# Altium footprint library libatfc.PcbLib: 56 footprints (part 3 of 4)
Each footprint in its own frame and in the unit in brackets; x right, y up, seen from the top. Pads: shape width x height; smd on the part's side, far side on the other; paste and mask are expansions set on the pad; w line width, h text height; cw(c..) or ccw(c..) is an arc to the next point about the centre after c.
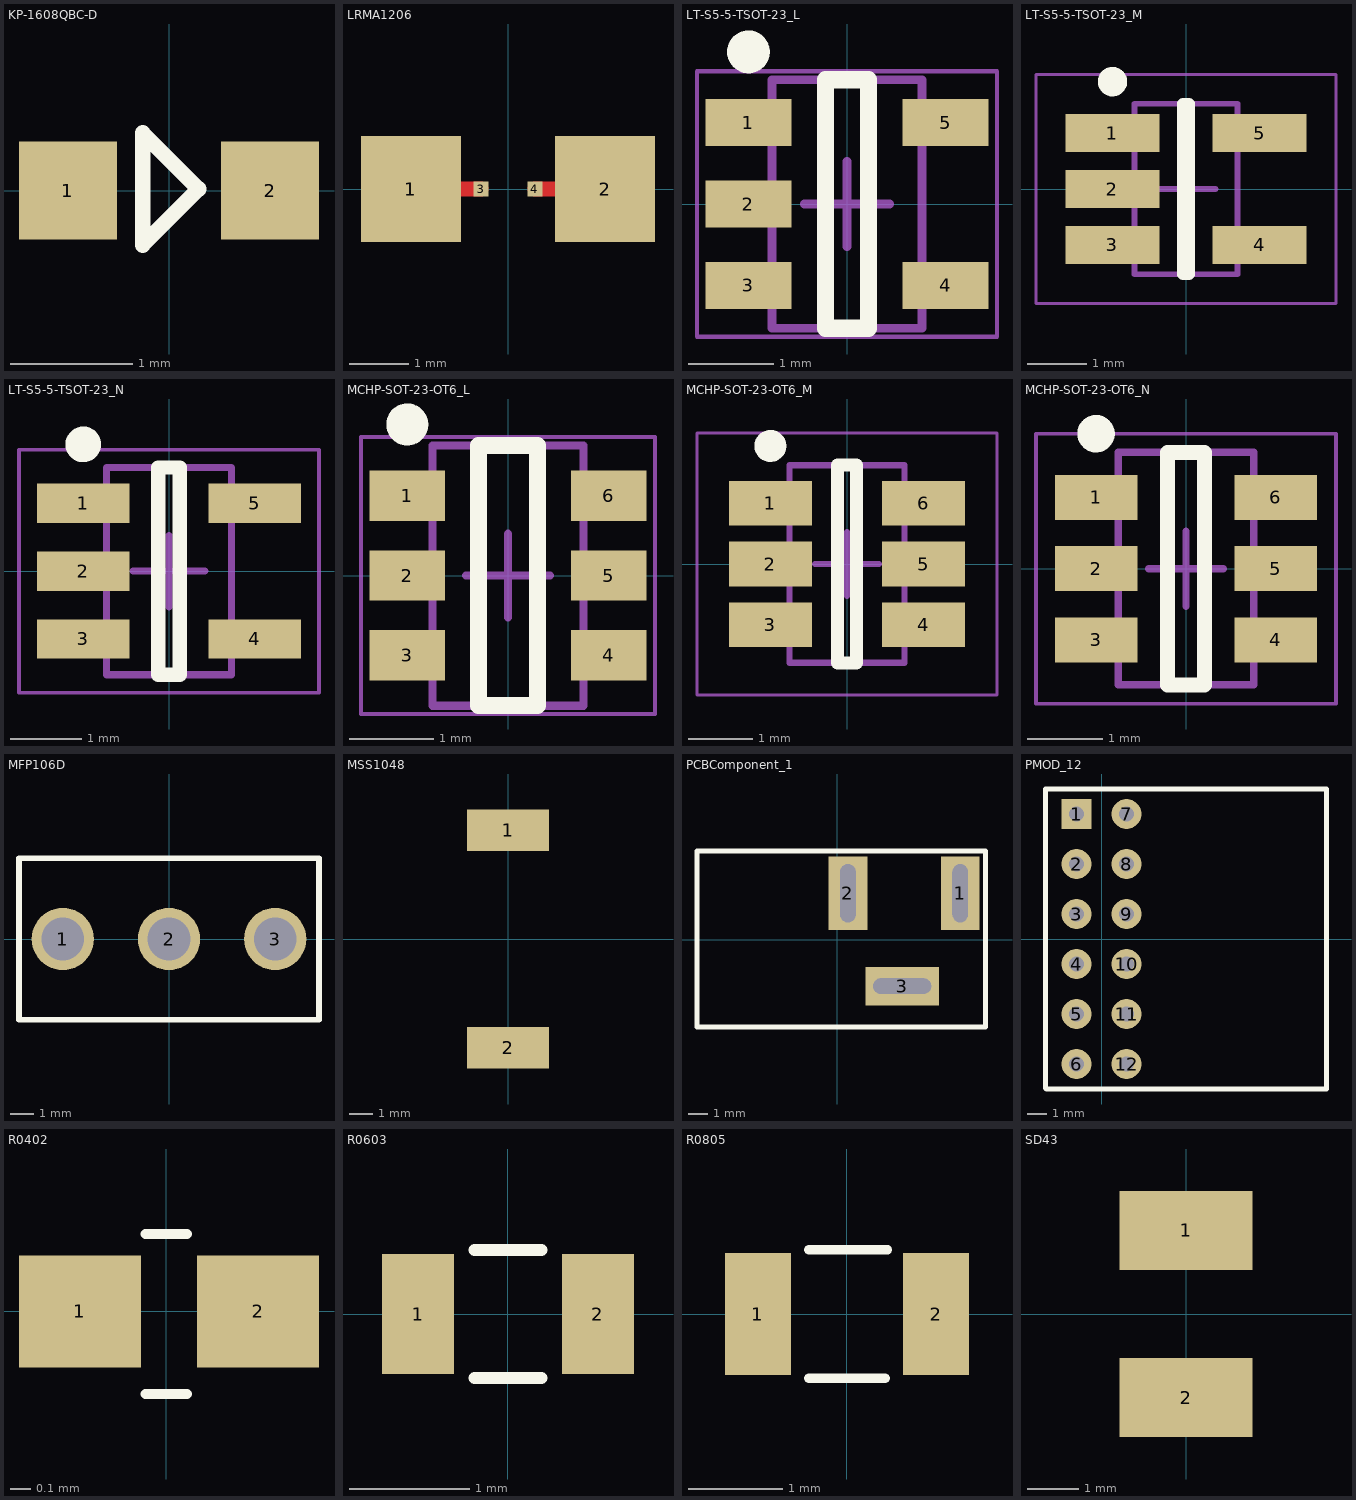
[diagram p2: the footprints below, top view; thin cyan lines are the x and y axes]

## KP-1608QBC-D [mm]
pads (2):
  rect 0.8x0.8 smd: 1(-0.825,0) 2(0.825,0)
Top Overlay:
  lines w0.127: -0.216,-0.445 -0.216,0.47 0.241,0.013 -0.216,-0.445

## LRMA1206 [mm]
pads (4):
  rect 1.7x1.8 smd: 1(-1.65,0) 2(1.65,0)
  rect 0.254x0.254 smd: 3(-0.457,0) 4(0.457,0)
Top Layer:
  lines w0.254: -1.65,0 -0.457,0 ; 0.457,0 1.625,0

## LT-S5-5-TSOT-23_L [mm] "SOT23, 5-Leads, Body 2.90x1.63mm, Pitch 0.95mm, IPC High Density"
height 1
pads (5):
  rect 1x0.55 smd: 1(-1.15,0.95) 2(-1.15,0) 3(-1.15,-0.95) 4(1.15,-0.95) 5(1.15,0.95)
Top Overlay:
  circle w0.25: c-1.15,1.775 r0.125
  lines w0.2: -0.25,-1.45 0.25,-1.45 0.25,1.45 -0.25,1.45 -0.25,-1.45
Mechanical 13:
  lines w0.1: -0.875,-1.45 -0.875,1.45 0.875,1.45 0.875,-1.45 -0.875,-1.45
Mechanical 15:
  lines w0.05: -1.75,-1.55 -1.75,1.55 1.75,1.55 1.75,-1.55 -1.75,-1.55
  lines w0.1: -0.5,0 0.5,0 ; 0,-0.5 0,0.5
3D body: height 1, standoff 0.01, extent -0.875,-1.45 0.875,1.45

## LT-S5-5-TSOT-23_M [mm] "SOT23, 5-Leads, Body 2.90x1.63mm, Pitch 0.95mm, IPC Low Density"
height 1
pads (5):
  rect 1.6x0.65 smd: 1(-1.25,0.95) 2(-1.25,0) 3(-1.25,-0.95) 4(1.25,-0.95) 5(1.25,0.95)
Top Overlay:
  circle w0.25: c-1.25,1.825 r0.125
  lines w0.2: -0.05,-1.45 -0.05,1.45 0.05,1.45 0.05,-1.45 -0.05,-1.45
Mechanical 13:
  lines w0.1: -0.875,-1.45 0.875,-1.45 0.875,1.45 -0.875,1.45 -0.875,-1.45
Mechanical 15:
  lines w0.05: -2.55,-1.95 2.55,-1.95 2.55,1.95 -2.55,1.95 -2.55,-1.95
  lines w0.1: -0.5,0 0.5,0 ; 0,-0.5 0,0.5
3D body: height 1, standoff 0.01, extent -0.875,-1.45 0.875,1.45

## LT-S5-5-TSOT-23_N [mm] "SOT23, 5-Leads, Body 2.90x1.63mm, Pitch 0.95mm, IPC Medium Density"
height 1
pads (5):
  rect 1.3x0.55 smd: 1(-1.2,0.95) 2(-1.2,0) 3(-1.2,-0.95) 4(1.2,-0.95) 5(1.2,0.95)
Top Overlay:
  circle w0.25: c-1.2,1.775 r0.125
  lines w0.2: -0.15,-1.45 0.15,-1.45 0.15,1.45 -0.15,1.45 -0.15,-1.45
Mechanical 13:
  lines w0.1: -0.875,-1.45 -0.875,1.45 0.875,1.45 0.875,-1.45 -0.875,-1.45
Mechanical 15:
  lines w0.05: -2.1,-1.7 -2.1,1.7 2.1,1.7 2.1,-1.7 -2.1,-1.7
  lines w0.1: -0.5,0 0.5,0 ; 0,-0.5 0,0.5
3D body: height 1, standoff 0.01, extent -0.875,-1.45 0.875,1.45

## MCHP-SOT-23-OT6_L [mm] "SOT23, 6-Leads, Body 2.9x1.55mm, Pitch 0.95mm, IPC High Density"
height 1.45
pads (6):
  rect 0.9x0.6 smd: 1(-1.2,0.95) 2(-1.2,0) 3(-1.2,-0.95) 4(1.2,-0.95) 5(1.2,0) 6(1.2,0.95)
Top Overlay:
  circle w0.25: c-1.2,1.8 r0.125
  lines w0.2: -0.35,-1.55 -0.35,1.55 0.35,1.55 0.35,-1.55 -0.35,-1.55
Mechanical 13:
  lines w0.1: -0.9,-1.55 0.9,-1.55 0.9,1.55 -0.9,1.55 -0.9,-1.55
Mechanical 15:
  lines w0.05: -1.75,-1.65 1.75,-1.65 1.75,1.65 -1.75,1.65 -1.75,-1.65
  lines w0.1: -0.5,0 0.5,0 ; 0,-0.5 0,0.5
3D body: height 1.45, standoff 0, extent -0.9,-1.55 0.9,1.55

## MCHP-SOT-23-OT6_M [mm] "SOT23, 6-Leads, Body 2.9x1.55mm, Pitch 0.95mm, IPC Low Density"
height 1.45
pads (6):
  rect 1.3x0.7 smd: 1(-1.2,0.95) 2(-1.2,0) 3(-1.2,-0.95) 4(1.2,-0.95) 5(1.2,0) 6(1.2,0.95)
Top Overlay:
  circle w0.25: c-1.2,1.85 r0.125
  lines w0.2: -0.15,-1.55 0.15,-1.55 0.15,1.55 -0.15,1.55 -0.15,-1.55
Mechanical 13:
  lines w0.1: -0.9,-1.55 -0.9,1.55 0.9,1.55 0.9,-1.55 -0.9,-1.55
Mechanical 15:
  lines w0.05: -2.35,-2.05 -2.35,2.05 2.35,2.05 2.35,-2.05 -2.35,-2.05
  lines w0.1: -0.5,0 0.5,0 ; 0,-0.5 0,0.5
3D body: height 1.45, standoff 0, extent -0.9,-1.55 0.9,1.55

## MCHP-SOT-23-OT6_N [mm] "SOT23, 6-Leads, Body 2.9x1.55mm, Pitch 0.95mm, IPC Medium Density"
height 1.45
pads (6):
  rect 1.1x0.6 smd: 1(-1.2,0.95) 2(-1.2,0) 3(-1.2,-0.95) 4(1.2,-0.95) 5(1.2,0) 6(1.2,0.95)
Top Overlay:
  circle w0.25: c-1.2,1.8 r0.125
  lines w0.2: -0.25,-1.55 -0.25,1.55 0.25,1.55 0.25,-1.55 -0.25,-1.55
Mechanical 13:
  lines w0.1: -0.9,-1.55 0.9,-1.55 0.9,1.55 -0.9,1.55 -0.9,-1.55
Mechanical 15:
  lines w0.05: -2,-1.8 2,-1.8 2,1.8 -2,1.8 -2,-1.8
  lines w0.1: -0.5,0 0.5,0 ; 0,-0.5 0,0.5
3D body: height 1.45, standoff 0, extent -0.9,-1.55 0.9,1.55

## MFP106D [mm]
pads (3):
  round 2.7 hole 1.85: 1(-4.6,0) 2(0,0) 3(4.6,0)
Top Overlay:
  lines w0.254: -6.5,-3.5 -6.5,3.5 6.5,3.5 6.5,-3.5 -6.5,-3.5

## MSS1048 [mm]
pads (2):
  rect 3.56x1.78 smd: 1(0,4.7) 2(0,-4.7)
3D body "Coilcraft-MSS1048.step": height 5, standoff -0.1, extent -5.227,-5.15 4.973,5.15

## PCBComponent_1 [mm]
pads (3):
  rect 2x3.8 hole 0.8 slot 3 at 90 deg: 1(6.35,2.4) 2(0.55,2.4)
  rect 3.8x2 hole 0.8 slot 3 at 0 deg: 3(3.35,-2.4)
Top Overlay:
  lines w0.254: -7.25,-4.5 -7.25,4.572 7.645,4.572 7.645,-4.5 -7.25,-4.5

## PMOD_12 [mil]
pads (12):
  rect 60x60 hole 30: 1(-50,250)
  round 60 hole 30: 2(-50,150) 3(-50,50) 4(-50,-50) 5(-50,-150) 6(-50,-250) 7(50,250) 8(50,150) 9(50,50) 10(50,-50) 11(50,-150) 12(50,-250)
Top Overlay:
  lines w10: -112,-298 -112,-269 -112,300 450,300 450,-300 -110,-300 -112,-298
3D body "female_header_a-bl254-da-g12d.stp": height 198.43, standoff -124.41, extent -48.42,-305.93 447.64,303.91

## R0402 [mm]
pads (2):
  rect 0.6x0.55 smd: 1(-0.425,0) 2(0.452,0)
Top Overlay:
  lines w0.051: -0.102,-0.406 0.102,-0.406 ; -0.102,0.381 0.102,0.381
3D body: height 0.35, standoff 0, extent -0.54,-0.254 -0.381,0.254
3D body: height 0.35, standoff 0, extent -0.381,-0.254 0.381,0.254
3D body: height 0.35, standoff 0, extent 0.381,-0.254 0.54,0.254

## R0603 [mm]
pads (2):
  rect 0.6x1 smd: 1(-0.75,0) 2(0.75,0)
Top Overlay:
  lines w0.1: -0.279,-0.533 0.279,-0.533 ; -0.279,0.533 0.279,0.533
3D body: height 0.35, standoff 0, extent -0.508,-0.444 0.508,0.445
3D body: height 0.35, standoff 0, extent 0.508,-0.444 0.762,0.445
3D body: height 0.35, standoff 0, extent -0.762,-0.444 -0.508,0.445

## R0805 [mm]
pads (2):
  rect 0.7x1.3 smd: 1(-0.95,0) 2(0.95,0)
Top Overlay:
  lines w0.1: -0.406,-0.686 0.406,-0.686 ; -0.406,0.686 0.432,0.686
3D body: height 0.35, standoff 0, extent 0.762,-0.603 1.016,0.603
3D body: height 0.35, standoff 0, extent -0.762,-0.603 0.762,0.603
3D body: height 0.35, standoff 0, extent -1.016,-0.603 -0.762,0.603

## SD43 [mm]
pads (2):
  rect 2.6x1.55 smd: 1(0,1.64) 2(0,-1.64)
3D body "Coilcraft-SD43.STEP": height 3.45, standoff 0, extent -2.1,-2.314 2.1,2.314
